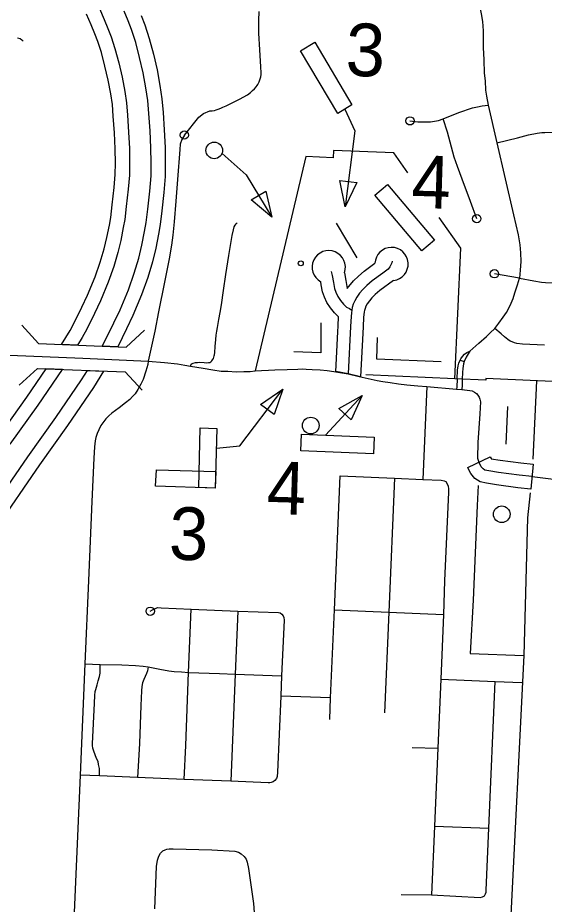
# Model space of a CAD drawing. Extents: x 653372 to 905732, y 627442 to 787275.
# Drawn here: x 673100 to 676268, y 745249 to 750580 of the extents above; entities that cross this region are included whole.
import ezdxf

# ---------------------------------------------------------------- set-up
doc = ezdxf.new("R2010")
doc.units = 0
for name, color, linetype in [('19', 7, 'Continuous'), ('31', 7, 'Continuous'), ('33', 7, 'Continuous'), ('34', 7, 'Continuous'), ('39', 7, 'Continuous'), ('5', 7, 'Continuous'), ('56', 7, 'Continuous'), ('6', 7, 'Continuous')]:
    doc.layers.add(name, color=color, linetype=linetype)

msp = doc.modelspace()

# ---------------------------------------------------------------- linework, layer by layer
at = {"layer": '19'}
for points in [[(673592.2, 750635.6), (673620.5, 750570.2), (673642.6, 750514.8), (673661.9, 750464.8), (673684.8, 750394.8), (673707.1, 750309.9), (673727.4, 750222.4), (673743.2, 750136.6), (673754, 750068.3), (673759.5, 749994.1), (673766.5, 749892.8), (673771.5, 749794), (673772.2, 749706.7), (673772, 749634.2), (673764.9, 749549.8), (673752.5, 749444.4), (673743.4, 749367.4)], [(673872.1, 749349.1), (673881.6, 749429.2), (673894.3, 749536.8), (673901.9, 749628.6), (673902.2, 749707), (673901.5, 749797.8), (673896.3, 749900.6), (673889.2, 750003.4), (673883.2, 750083.3), (673871.4, 750158.5), (673854.7, 750248.9), (673833.3, 750341.1), (673809.6, 750431.5), (673784.4, 750508.5), (673763.6, 750562.2), (673740.6, 750620.1)], [(673659.2, 749379.4), (673668.1, 749454.4), (673680.3, 749558.3), (673687, 749637.9), (673687.2, 749706.5), (673686.5, 749791.5), (673681.7, 749887.8), (673674.8, 749988), (673669.5, 750058.5), (673659.4, 750122.3), (673644.2, 750205.1), (673624.5, 750289.5), (673603.2, 750370.8), (673581.8, 750436.3), (673563.5, 750483.7), (673542, 750537.5), (673514.5, 750601.1)], [(673842.8, 750593.3), (673864.5, 750537), (673891.1, 750455.5), (673915.8, 750361.5), (673938, 750266.3), (673955.2, 750172.8), (673967.7, 750093.1), (673974, 750009.5), (673981.2, 749905.6), (673986.5, 749800.2), (673987.2, 749707.2), (673986.9, 749624.9), (673978.9, 749528.3), (673966, 749419.2), (673956.3, 749337.1)], [(673460.2, 748611.9), (673363.1, 748615.9), (673414.4, 748700.2), (673439.2, 748745.6), (673484.5, 748838.7), (673519.3, 748912.2), (673565.5, 749021.4), (673596.6, 749109.9), (673620.2, 749189.7), (673636.8, 749258.9), (673651.5, 749333), (673659.2, 749379.4)], [(673743.4, 749367.4), (673735.1, 749317.8), (673719.9, 749240.7), (673702.3, 749167.8), (673677.6, 749083.8), (673644.8, 748990.6), (673596.9, 748877.5), (673561.2, 748802), (673514.8, 748706.6), (673488, 748657.7), (673460.2, 748611.9)], [(673607.8, 748605.8), (673630.3, 748647), (673678.4, 748745.8), (673715.5, 748824.4), (673766.1, 748943.7), (673801.3, 749043.8), (673827.9, 749134.1), (673846.9, 749212.8), (673863, 749294.6), (673872.1, 749349.1)], [(673956.3, 749337.1), (673946.7, 749279.3), (673929.9, 749194.7), (673910.1, 749112.1), (673882.2, 749017.7), (673845.4, 748913), (673793.1, 748789.6), (673755.1, 748709), (673702.9, 748601.9), (673607.8, 748605.8)], [(672891.1, 747550.4), (673161, 747940.3), (673328.6, 748176.1), (673484.1, 748403.2), (673519.1, 748459.4)], [(673519.1, 748459.4), (673616.7, 748455.3), (673555.2, 748356.7), (673398.3, 748127.5), (673230.6, 747891.5), (672961.1, 747502.1)], [(673369.2, 748465.5), (673269, 748469.6), (673152.3, 748299.1), (672985, 748063.8)], [(673054.6, 748014.9), (673222, 748250.5), (673369.2, 748465.5)]]:
    msp.add_lwpolyline(points, dxfattribs=at)
at = {"layer": '31'}
for p, q in [((675025.8, 748690.5), (675025.8, 748690.5)), ((676201.8, 747894.9), (676186, 747745.7))]:
    msp.add_line(p, q, dxfattribs=at)
for points in [[(675082.3, 748951.3), (675120.8, 748997.7), (675149.6, 749025.5), (675184.8, 749056.1), (675248.7, 749103.5)], [(675351.6, 749115.5), (675350.1, 749105.7), (675345.1, 749093.2), (675339, 749081.2), (675328.2, 749068.2), (675295.7, 749044.9), (675231.8, 748997.6), (675200.3, 748970.2), (675175.9, 748946.6), (675156.7, 748923.5), (675139.2, 748899.7), (675127.5, 748878.1), (675118.8, 748858.1), (675112.4, 748836.9), (675110.2, 748822.5), (675107.4, 748804.6), (675105.1, 748784.4), (675102.7, 748724), (675087.7, 748438.4)], [(674986.5, 749054.7), (674992.1, 749030.3), (674999.5, 748987.2), (675006, 748951.7), (675014, 748928.9), (675025.9, 748903.7), (675041.4, 748879.5), (675059.8, 748857), (675077.8, 748840.2), (675094.9, 748831), (675110.2, 748822.5)], [(675065.3, 749047), (675073.4, 749000.3), (675082.3, 748951.3)], [(675029.9, 748782.3), (675005, 748805.5), (674980.6, 748835.4), (674960.2, 748867.3), (674944.5, 748900.4), (674933.2, 748932.5), (674925.6, 748974.2), (674922.5, 748992.5)], [(675361.1, 749000), (675278.8, 748939.1), (675251, 748914.9), (675230.9, 748895.6), (675215.8, 748877.3), (675202.7, 748859.5), (675195.1, 748845.3), (675189.3, 748832.2), (675185.8, 748820.3), (675184.4, 748811), (675181.7, 748794.4), (675179.9, 748778.6), (675177.6, 748720.5), (675175.6, 748682.6)], [(675025.8, 748690.5), (675027.7, 748727.4), (675029.9, 748782.3)], [(675161.9, 748420.5), (675087.7, 748438.4), (675013.3, 748452.2), (675025.8, 748690.5)], [(675175.6, 748682.6), (675161.9, 748420.5)], [(676186, 747745.7), (676108.2, 747753.9), (675980.3, 747771.1), (675919.8, 747781.2), (675881.7, 747789.8), (675849.3, 747809.3), (675825.6, 747838.8), (675814.2, 747860.6), (675807.2, 747875.2), (675942.4, 747940.1)], [(676193.9, 747820.3), (676117.1, 747828.4), (675991.4, 747845.2), (675934.3, 747854.8), (675910.1, 747860.3), (675899.4, 747866.7), (675888.7, 747880.1), (675881.2, 747894.2), (675874.8, 747907.6)], [(675942.4, 747940.1), (675948, 747928.6), (675948.8, 747928.4), (676002.6, 747919.4), (676126, 747902.9), (676201.8, 747894.9)]]:
    msp.add_lwpolyline(points, dxfattribs=at)
for centre, start, end in [((674971, 749080), 340.7218, 241.0164), ((675348.7, 749099.2), 277.1343, 177.559)]:
    msp.add_arc(centre, 100, start, end, dxfattribs=at)
at = {"layer": '33'}
for points in [[(675729.2, 751191.8), (675798.2, 750925.7), (675853.8, 750745.7), (675877.9, 750651.2), (675887.1, 750604), (675896.2, 750556.8), (675900.4, 750500.4), (675900.9, 750401.9), (675904.5, 750326.3), (675906.8, 750246.4), (675911.3, 750201.7), (675914.3, 750145.4), (675920.2, 750108.8), (675930.4, 750055), (675983.3, 749827.8), (676082.9, 749394.3), (676109.8, 749275), (676120.8, 749213.7), (676125.2, 749165.5), (676126.1, 749115.1), (676123.3, 749061.2), (676118.3, 749013.3)], [(674102.4, 749874.6), (674189.1, 749981.4), (674218.4, 750003.4), (674255.6, 750020.1), (674270.4, 750021.1), (674283, 750023.3), (674293.5, 750026.3), (674305.3, 750029.8), (674321.2, 750035.9), (674334.4, 750041.4), (674353.6, 750050.3), (674402.4, 750073.8), (674438.1, 750091.8), (674456.7, 750101.9), (674481.2, 750116.7), (674499.9, 750130.4), (674512.5, 750141.7), (674523.7, 750151.8), (674534, 750163.7), (674539.6, 750171.7), (674544.1, 750178.5), (674551.9, 750194.1), (674557.8, 750212.2), (674561.8, 750225.3), (674563.7, 750238), (674564.3, 750249.4), (674562.8, 750285.6), (674556.5, 750387.4), (674550.6, 750487.6), (674550.3, 750510.8), (674550.6, 750563.5), (674553.2, 750617.1)], [(673098.3, 750459.9), (673114.1, 750454.3), (673124, 750448.1), (673132.1, 750439)], [(675459.7, 749960.1), (675507.6, 749954), (675522.8, 749953.5), (675565, 749953.4), (675582.7, 749954.7), (675607.4, 749957.4), (675630.4, 749962.6), (675659.4, 749972.9), (675753.7, 750009.3), (675835.5, 750038), (675865, 750044.7), (675894.5, 750050.3), (675930.4, 750055)], [(675861.8, 749371.6), (675823.9, 749476), (675772.8, 749610), (675745.8, 749685.9), (675726.3, 749741.6), (675686.3, 749891.1), (675659.4, 749972.9)], [(674102.4, 749874.6), (674086.5, 749847.4), (674077, 749819.6), (674074.1, 749788), (674060.1, 749606.5), (674050.1, 749476.5), (674040.7, 749352.5), (674032.1, 749271.8), (674024.1, 749212), (674010.9, 749130.9), (673982.9, 748990.8), (673946.8, 748812.5), (673924.1, 748696.1), (673885.2, 748514.2)], [(675983.3, 749827.8), (676106.2, 749858.7), (676173.5, 749876), (676224.8, 749886.2), (676252.5, 749889.5), (676270.1, 749890.1), (676324.1, 749892), (676365.6, 749890.8), (676390.9, 749887.1), (676427.3, 749881.9), (676486.7, 749870.7), (676539.5, 749858.6), (676582.5, 749847.3), (676640.4, 749833.9), (676677, 749822.2), (676742.3, 749799.7), (676803.6, 749773.3), (676834.2, 749756.5), (676863, 749738.1), (676905.5, 749710.4), (676962.2, 749665.3), (677004, 749633), (677060.5, 749582.6)], [(676118.3, 749013.3), (675967.9, 749040.1)], [(675819.4, 748575.9), (675874.4, 748622.1), (675919.7, 748663.7), (675941.3, 748685.1), (675969.3, 748712), (675994.2, 748743.9), (676020.2, 748779.6), (676039.6, 748807.8), (676055.1, 748834), (676069, 748863), (676079.6, 748891.4), (676091.5, 748924.9), (676106.6, 748973.8), (676118.3, 749013.3)], [(676118.3, 749013.3), (676204.6, 748997), (676251.7, 748989.6), (676275.4, 748987.2), (676324.3, 748986.3), (676611.4, 748970.1)], [(676269.2, 748611), (676136.6, 748617.7), (676103, 748620.8), (676088.5, 748625.6), (676075, 748630.4), (676062.6, 748635.7), (676048.8, 748644.8), (676028, 748660.6), (676007.4, 748678.7), (675969.3, 748712)], [(671652.5, 748606.5), (671745.1, 748603.4), (672147.5, 748587.3), (672556.3, 748570.1), (673492.2, 748532.9)], [(675743.7, 748408.4), (675746.3, 748461.1), (675749.3, 748487.4), (675753.6, 748503.8), (675761.4, 748520.5), (675765.8, 748528), (675774.9, 748542.4), (675788.6, 748556.4), (675802.2, 748566), (675819.4, 748575.9), (675809.4, 748559.6), (675797.4, 748539.3), (675785.4, 748512.7), (675781.7, 748498.6), (675778.2, 748471), (675776.4, 748447.1), (675774.1, 748407.1)], [(673885.2, 748514.2), (673881.8, 748495.3), (673869.6, 748453.9), (673854.6, 748405.4), (673841.2, 748375.6), (673822, 748343.8), (673805.6, 748319.3), (673791, 748302), (673774.9, 748284.2), (673748.8, 748265.2), (673709.8, 748235.1), (673666.1, 748203), (673648.9, 748186.4), (673629.6, 748167.1), (673617.2, 748152.5), (673600.3, 748127.5), (673587.5, 748102.3), (673578, 748079.7), (673570.5, 748056.5), (673566.2, 748035.2), (673562, 747999.3), (673557.4, 747931.1), (673545.9, 747671.3), (673526.5, 747196.6), (673503.5, 746693.7), (673475, 746026.1), (673431.2, 745015.8)], [(673492.2, 748532.9), (673885.2, 748514.2), (673983, 748506.6), (674061.4, 748498.5), (674105.2, 748490.2), (674138.5, 748484.7), (674214.5, 748471.9), (674274.4, 748463.1), (674324.5, 748455.3), (674363.8, 748454.1), (674414.6, 748451.4), (674459.2, 748453), (674499.1, 748452.9), (674529.3, 748456.1), (674566.3, 748457.8), (674609.2, 748460), (674646.5, 748461.8), (674721.7, 748464.7), (674784.9, 748467.5), (674813.2, 748467.8), (674835.8, 748467.1), (674871, 748465.5), (674919.5, 748462.9), (674961, 748458.1), (675002.5, 748453.4), (675038.7, 748446.5), (675087.7, 748438.4)], [(675761.4, 748520.5), (675785.4, 748512.7)], [(675087.7, 748438.4), (675154.3, 748422.2), (675226.7, 748405.6), (675262.9, 748398.2), (675296.3, 748393.1), (675340.6, 748386), (675390.1, 748378.7), (675441.4, 748373.1), (675507.2, 748366.5), (675561.5, 748361.7), (675739.5, 748346.5), (675771, 748343.5)], [(675743.7, 748408.4), (675741.1, 748358.9), (675739.5, 748346.5)], [(675774.1, 748407.1), (675773, 748370), (675771, 748343.5)], [(675561.5, 748361.7), (675536.5, 747802.3)], [(675771, 748343.5), (675819.3, 748338.5), (675833.9, 748335.5), (675848.4, 748328.4), (675859.6, 748319.4), (675867.5, 748311), (675875.8, 748298.2), (675880.9, 748286.2), (675883.1, 748270.9), (675881, 748199.1), (675868.5, 748025.2), (675866.4, 747931.9), (675874.8, 747907.6)], [(674977.3, 746360.5), (674981.5, 746489.3), (675006.4, 747018.8), (675040.5, 747824.6)], [(675040.5, 747824.6), (675366.9, 747811.2), (675536.5, 747802.3), (675646.9, 747799.2), (675664.8, 747795.8), (675675.4, 747790.4), (675684.4, 747777.9), (675689, 747764.1), (675692.1, 747746.7), (675691.6, 747728), (675668.3, 747194), (675660.8, 746991.5), (675646.2, 746601.6), (675628, 746187.1), (675606.4, 745717.9), (675590, 745304.6)], [(675366.9, 747811.2), (675332.8, 747004.9), (675307.3, 746400.2)], [(676193.9, 747820.3), (676387.5, 747796.2)], [(673896.9, 747011.2), (673910.9, 747019.4), (673928.3, 747028), (673941.6, 747032.8), (673963.3, 747032.1), (674143.2, 747022.6), (674424, 747012), (674668.9, 747002.9), (674677.9, 747000.4), (674688.6, 746993.2), (674696.9, 746983.2), (674700.5, 746972.8), (674702.4, 746957.3), (674687.2, 746623.3), (674683.5, 746500.5), (674662.9, 746043.6), (674661.5, 746016.8), (674656.1, 746005.5), (674647.1, 745993.2), (674637.2, 745985.5), (674625, 745980.2), (674616.4, 745978.1), (674606.7, 745978.4), (674382.4, 745988.6), (674101.2, 745998.7), (673820.5, 746011.2), (673592, 746022), (673475, 746026.1)], [(674101.2, 745998.7), (674111.2, 746203.7), (674127.3, 746643.4), (674143.2, 747022.6)], [(674424, 747012), (674407.5, 746632.9), (674382.4, 745988.6)], [(675006.4, 747018.8), (675332.8, 747004.9), (675660.8, 746991.5)], [(673503.5, 746693.7), (673595, 746691.5), (673725.2, 746688.8), (673809.1, 746685.1), (673853.5, 746680.5), (673884, 746675.8), (673914.4, 746671.1), (673955.5, 746663), (674009.5, 746652.8), (674040.8, 746648.5), (674085.3, 746646), (674127.3, 746643.4), (674314.2, 746637.4), (674407.5, 746632.9), (674687.2, 746623.3)], [(673592, 746022), (673592.6, 746043.2), (673591.6, 746064.9), (673586.6, 746089.1), (673583.1, 746106.9), (673574.5, 746124.9), (673564.9, 746148), (673557.6, 746169.4), (673552.4, 746186.7), (673550, 746203.4), (673550.4, 746214.2), (673561.7, 746457.4), (673563.7, 746504.9), (673565.5, 746528.9), (673569.3, 746541.3), (673577.5, 746567.9), (673583.4, 746592.4), (673591.7, 746619), (673595.7, 746638.9), (673595.7, 746657.7), (673595, 746691.5)], [(673884, 746675.8), (673880.7, 746652), (673874.5, 746635.6), (673858.6, 746600.7), (673851.1, 746580.9), (673846.5, 746559.3), (673844, 746533.1), (673840.7, 746444), (673831.5, 746214.9), (673820.5, 746011.2)], [(675406.5, 745308), (675590, 745304.6), (675881.8, 745290.1), (675897, 745292.5), (675907.3, 745300.1), (675914.1, 745310.7), (675917.4, 745322.2), (675918.4, 745332.9), (675933.6, 745705.9), (675972.4, 746587.7)], [(675646.2, 746601.6), (675972.4, 746587.7), (676132.7, 746582.1)], [(674981.5, 746489.3), (674683.5, 746500.5)], [(675473.8, 746191.4), (675628, 746187.1)], [(675606.4, 745717.9), (675933.6, 745705.9)], [(673925, 745220.4), (673934.9, 745474.9), (673940.7, 745514.1), (673947.8, 745537), (673958.2, 745555.2), (673973.6, 745569.2), (673986, 745576.4), (673997.7, 745579.5), (674011.6, 745581.4), (674034.8, 745581.9), (674267.9, 745575.5), (674406.8, 745568.4), (674427.5, 745562.6), (674444.5, 745552.8), (674462.5, 745535.5), (674473.7, 745520.7), (674480, 745501.9), (674487.6, 745464.1), (674518.9, 745252.9), (674525.1, 745170.5)]]:
    msp.add_lwpolyline(points, dxfattribs=at)
for centre in [(675459.7, 749960.1), (675861.8, 749371.6), (675967.9, 749040.1), (673896.9, 747011.2)]:
    msp.add_circle(centre, 25, dxfattribs=at)
at = {"layer": '34'}
msp.add_lwpolyline([(674138.5, 748484.7), (674140.3, 748489.4), (674143.3, 748495.9), (674149.2, 748501.2), (674155.6, 748503.5), (674169.3, 748506.3), (674182.1, 748507.5), (674196.3, 748508), (674220.7, 748506.9), (674236.3, 748505.8), (674247, 748506.2), (674255, 748507.8), (674260.8, 748511.1), (674268.3, 748517.6), (674272.3, 748523.2), (674277.3, 748531.6), (674280.4, 748538.8), (674282.5, 748546), (674283.6, 748552), (674285.4, 748567.8), (674288.3, 748603), (674291.8, 748645.4), (674294.2, 748672), (674298.4, 748696), (674301.9, 748716.9), (674309.4, 748764.6), (674317.3, 748808.2), (674324.8, 748854.6), (674337.5, 748940.6), (674352.4, 749036.9), (674370, 749150.2), (674389.5, 749270.9), (674397.2, 749304), (674402.5, 749322.6), (674408.2, 749333.2), (674414.5, 749341.6), (674419.4, 749345.9)], dxfattribs=at)
msp.add_circle((674102.4, 749874.6), 25, dxfattribs=at)
at = {"layer": '39'}
for p, q in [((673225.4, 748621.6), (673753, 748599.9)), ((673219.3, 748471.7), (673746.8, 748450))]:
    msp.add_line(p, q, dxfattribs=at)
for points in [[(673123.8, 748731.9), (673225.4, 748621.6)], [(673753, 748599.9), (673863.3, 748701.5)], [(673219.3, 748471.7), (673108.9, 748370.1)], [(673848.4, 748339.7), (673746.8, 748450)]]:
    msp.add_lwpolyline(points, dxfattribs=at)
at = {"layer": '5'}
msp.add_lwpolyline([(675730.1, 748409), (675193.5, 748432.9)], dxfattribs=at)
at = {"layer": '56'}
for p, q in [((675070.2, 749443.9), (675038.6, 749602.1)), ((675038.6, 749602.1), (675139.8, 749589.4)), ((675139.8, 749589.4), (675070.2, 749443.9)), ((674505.2, 749485.6), (674592.6, 749538)), ((674592.6, 749538), (674627.6, 749380.6)), ((674627.6, 749380.6), (674505.2, 749485.6)), ((674560.8, 748254.8), (674693.9, 748345.8)), ((674693.9, 748345.8), (674642, 748193.1)), ((675030.8, 748230.8), (675172.4, 748308)), ((675172.4, 748308), (675105.5, 748161.3)), ((674642, 748193.1), (674560.8, 748254.8)), ((675105.5, 748161.3), (675030.8, 748230.8))]:
    msp.add_line(p, q, dxfattribs=at)
for points in [[(674801.8, 750381.3), (674887.8, 750432.3), (675110.7, 750055.8), (675024.7, 750004.9)], [(675249, 749512.7), (675325.3, 749577.3), (675608.1, 749243.5), (675531.8, 749178.8)], [(674288.5, 747750.9), (674188.5, 747754.5), (674198.1, 748113.4), (674298, 748109.8)], [(674803.6, 747975.8), (674807.8, 748075.7), (675244.9, 748057.7), (675240.8, 747957.8)], [(673929.6, 747762.2), (673933.7, 747862.1), (674292.6, 747850.8), (674288.5, 747750.9)]]:
    msp.add_lwpolyline(points, close=True, dxfattribs=at)
for points in [[(675067.7, 750030.3), (675127.5, 749900.1), (675070.2, 749443.9)], [(674330.2, 749764.1), (674474.3, 749636.3), (674627.6, 749380.6)], [(675014.9, 749345.3), (675139.4, 749136.6)], [(674923.8, 748744.5), (674922.8, 748565.8), (674761.6, 748570.6)], [(675647, 748510.2), (675259.5, 748526.2), (675263.4, 748656.9)], [(674294.9, 747991.4), (674435.1, 748004.7), (674693.9, 748345.8)], [(674950.7, 748069.8), (675172.4, 748308)], [(676046.4, 748242.8), (676036.9, 748016.3)]]:
    msp.add_lwpolyline(points, dxfattribs=at)
for centre, radius in [((674282.3, 749782.2), 50), ((674802.7, 749103.1), 15), ((674862.6, 748127.7), 50), ((676011.6, 747593.9), 50)]:
    msp.add_circle(centre, radius, dxfattribs=at)
at = {"layer": '6'}
for points in [[(675446.8, 749647.7), (675363.2, 749767), (674999.7, 749782.7), (674997.8, 749737.6), (674832.6, 749744.9), (674529.1, 748456.1)], [(676934.4, 747704.8), (676968.8, 748363.5), (676226.9, 748396), (675916.5, 748410.9), (675916.2, 748400.7), (675730.1, 748409), (675764.9, 749193.8), (675635.4, 749378.6)], [(676221.8, 748396.2), (676199, 747925.3)], [(675869.2, 747766.6), (675864.4, 747647.6), (675840.9, 747076.8), (675822.7, 746756.9), (676144.7, 746745), (676062, 745105.1)], [(676183.3, 747722.3), (676166.9, 747572.1), (676144.7, 746745)]]:
    msp.add_lwpolyline(points, dxfattribs=at)

# ---------------------------------------------------------------- texts
at = {"layer": '56'}
for s, p in [('3', (675069.8, 750231.8)), ('4', (675465.6, 749437.7)), ('4', (674595, 747597.2)), ('3', (674006.9, 747322.7))]:
    msp.add_text(s, height=316.8, rotation=358.28, dxfattribs=at).set_placement(p)

doc.saveas('drawing.dxf')
